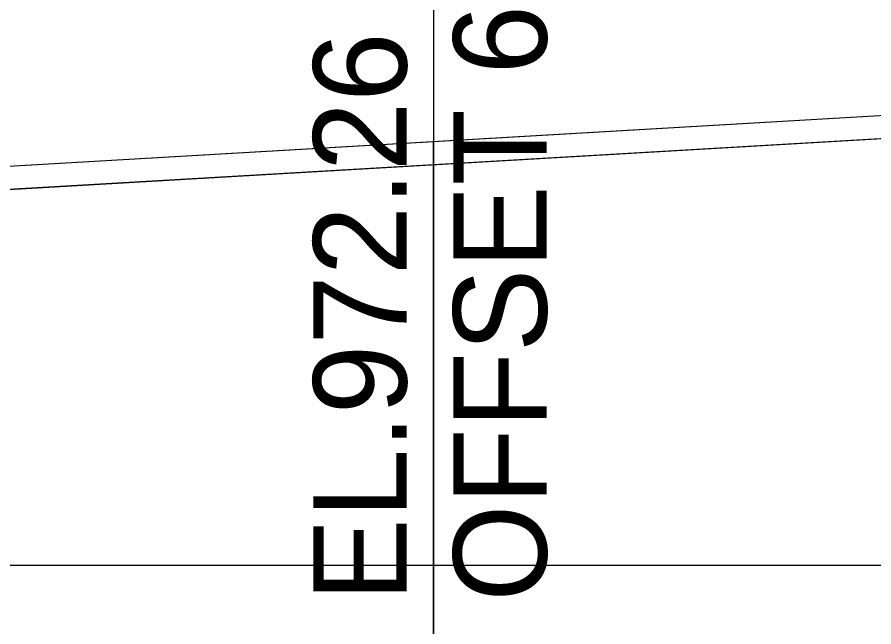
# Model space of a CAD drawing. Extents: x -120 to 2876, y -25 to 8560.
# Drawn here: x 1513.09 to 1522.27, y 1499.34 to 1505.87 of the extents above; entities that cross this region are included whole.
import ezdxf

# ---------------------------------------------------------------- set-up
doc = ezdxf.new("R2010")
doc.units = 0
for name, color, linetype in [('DESIGN - EARTHWORK - Excavation Limit Lines', 7, 'Continuous'), ('DESIGN - EARTHWORK - Shapes', 7, 'Continuous'), ('DESIGN - SHEET - Light Grid', 7, 'Continuous'), ('DESIGN - TYPICAL - Slope Tie Text', 7, 'Continuous'), ('SURVEY - GROUND - Bottom of Topsoil Layer', 7, 'Continuous'), ('SURVEY - GROUND - Top of Ground', 7, 'Continuous')]:
    doc.layers.add(name, color=color, linetype=linetype)

msp = doc.modelspace()

# ---------------------------------------------------------------- linework, layer by layer
at = {"layer": 'DESIGN - EARTHWORK - Excavation Limit Lines'}
msp.add_line((1517.55, 1522.5073), (1517.55, 1470.0073), dxfattribs=at)
at = {"layer": 'DESIGN - EARTHWORK - Shapes'}
for points in [[(1522.6379, 1504.8352), (1537.9767, 1505.2206), (1537.4502, 1504.9574), (1522.6379, 1504.5852), (1517.55, 1504.2884), (1517.55, 1504.5384)], [(1517.55, 1496.2573), (1520.05, 1496.2573), (1521.9327, 1497.1986), (1537.4502, 1504.9574), (1522.6379, 1504.5852), (1517.55, 1504.2884)], [(1512.5042, 1504.2441), (1517.55, 1504.5384), (1517.55, 1504.2884), (1512.5042, 1503.9941), (1509.6225, 1501.8448), (1508.7143, 1501.1306), (1506.2829, 1501.2487), (1505.0599, 1501.2523), (1504.557, 1501.5038), (1506.2829, 1501.4987), (1508.7143, 1501.3806), (1509.6225, 1502.0948)], [(1505.0599, 1501.2523), (1513.2677, 1497.1484), (1515.05, 1496.2573), (1517.55, 1496.2573), (1517.55, 1504.2884), (1512.5042, 1503.9941), (1509.6225, 1501.8448), (1508.7143, 1501.1306), (1506.2829, 1501.2487)]]:
    msp.add_lwpolyline(points, close=True, dxfattribs=at)
at = {"layer": 'DESIGN - SHEET - Light Grid'}
msp.add_line((1450, 1500), (1600, 1500), dxfattribs=at)
at = {"layer": 'SURVEY - GROUND - Bottom of Topsoil Layer'}
msp.add_line((1512.5042, 1503.9941), (1522.6379, 1504.5852), dxfattribs=at)
at = {"layer": 'SURVEY - GROUND - Top of Ground'}
msp.add_lwpolyline([(1473.8636, 1514.234), (1475.0768, 1514.1799), (1478.1177, 1514.0443), (1478.4544, 1514.0067), (1480.5843, 1513.7746), (1481.7653, 1513.7023), (1493.1042, 1506.5489), (1502.4024, 1501.5101), (1506.2829, 1501.4987), (1508.7143, 1501.3806), (1509.6225, 1502.0948), (1512.5042, 1504.2441), (1522.6379, 1504.8352), (1538.647, 1505.2375), (1563.2398, 1505.2476), (1590.2965, 1507.963), (1600, 1508.875)], dxfattribs=at)

# ---------------------------------------------------------------- texts
at = {"layer": 'DESIGN - TYPICAL - Slope Tie Text'}
for s, p in [('OFFSET 67.55', (1518.763, 1499.6094)), ('EL.972.26', (1517.263, 1499.6094))]:
    msp.add_text(s, height=1, rotation=90, dxfattribs=at).set_placement(p)

doc.saveas('drawing.dxf')
